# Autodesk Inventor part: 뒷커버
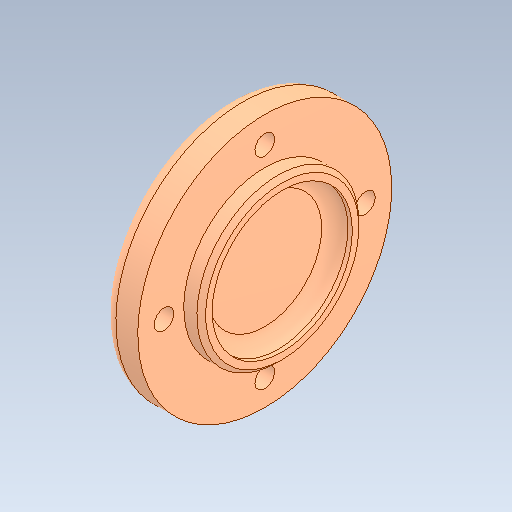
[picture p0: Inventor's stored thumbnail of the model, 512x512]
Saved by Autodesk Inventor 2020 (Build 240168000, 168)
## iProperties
Created: 2024-08
Part Number: 뒷커버
Material: 알루미늄 6061
Document SubType Name: Modeling
Designer: oem
Density: 2.7 g/cm^3
Appearance: 기본값
Author: jhkim
Sending System: Autodesk Inventor 2025
Preprocessor: ST-DEVELOPER v20
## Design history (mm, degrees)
node "뒷커버1"
node "솔리드2"
node "솔리드1"
